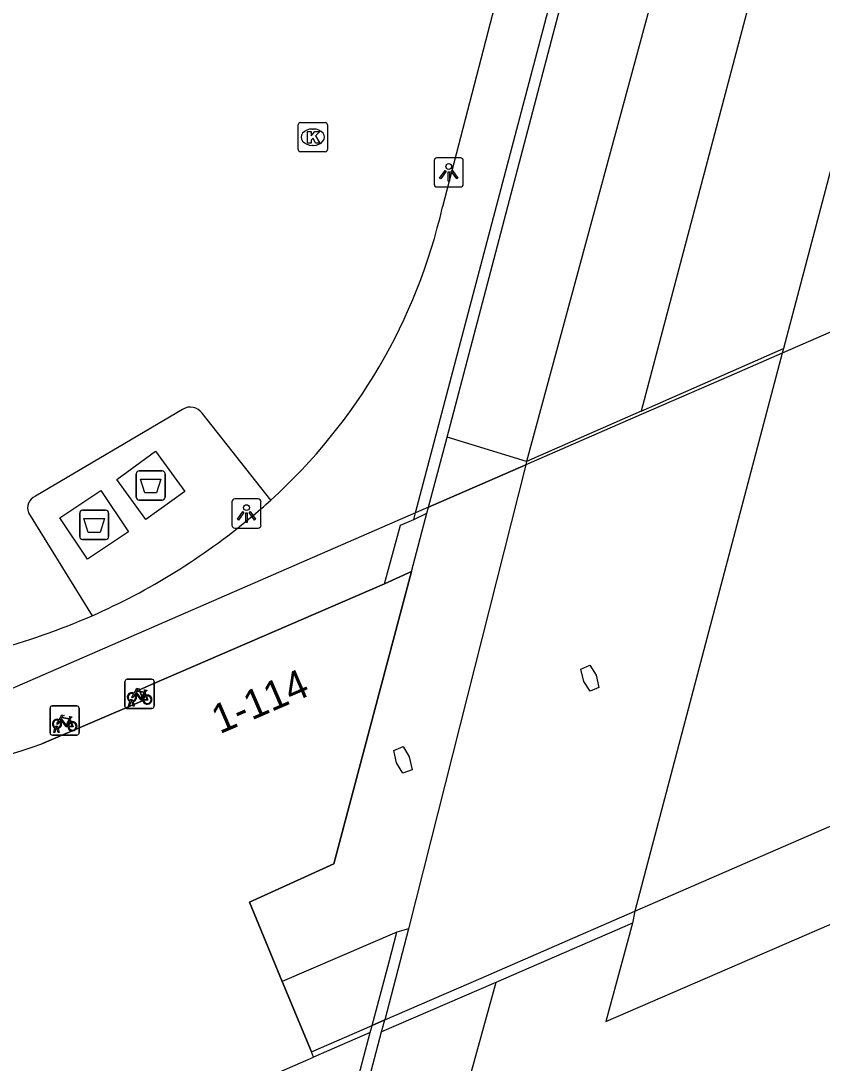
# Model space of a CAD drawing. Extents: x 162026 to 163499, y 387297 to 388169.
# Drawn here: x 162514.93 to 162542.4, y 387569.33 to 387605.06 of the extents above; entities that cross this region are included whole.
import ezdxf

# ---------------------------------------------------------------- set-up
doc = ezdxf.new("R2010")
doc.units = 0
for name, color, linetype in [('IMGEO_Afval_apart_plaats', 7, 'Continuous'), ('IMGEO_Fietsenrek', 7, 'Continuous'), ('IMGEO_Kolk', 7, 'Continuous'), ('IMGEO_Lichtpunt', 7, 'Continuous'), ('IMGEO_Meer_plas_ven_vijver', 7, 'Continuous'), ('IMGEO_Muur', 7, 'Continuous'), ('IMGEO_Pand', 7, 'Continuous'), ('IMGEO_Pand_nummerreeks', 7, 'Continuous'), ('IMGEO_Pand_overbouw', 7, 'Continuous'), ('IMGEO_Voetpad_gesloten', 7, 'Continuous'), ('IMGEO_Voetpad_halfverhard', 7, 'Continuous'), ('IMGEO_Voetpad_open', 7, 'Continuous')]:
    doc.layers.add(name, color=color, linetype=linetype)

msp = doc.modelspace()

# ---------------------------------------------------------------- linework, layer by layer
at = {"layer": 'IMGEO_Afval_apart_plaats'}
for p, q in [((162518.885, 387588.734), (162518.885, 387589.534)), ((162518.885, 387589.534), (162518.885, 387588.734)), ((162518.985, 387589.634), (162519.775, 387589.634)), ((162519.775, 387589.634), (162518.985, 387589.634)), ((162519.875, 387589.534), (162519.875, 387588.734)), ((162519.875, 387588.734), (162519.875, 387589.534)), ((162519.775, 387588.634), (162518.985, 387588.634)), ((162518.985, 387588.634), (162519.775, 387588.634)), ((162516.946, 387587.381), (162516.946, 387588.181)), ((162516.946, 387588.181), (162516.946, 387587.381)), ((162517.046, 387588.281), (162517.836, 387588.281)), ((162517.836, 387588.281), (162517.046, 387588.281)), ((162517.936, 387588.181), (162517.936, 387587.381)), ((162517.936, 387587.381), (162517.936, 387588.181)), ((162517.836, 387587.281), (162517.046, 387587.281)), ((162517.046, 387587.281), (162517.836, 387587.281))]:
    msp.add_line(p, q, dxfattribs=at)
for points in [[(162519.028, 387589.348), (162519.732, 387589.348), (162519.583, 387588.878), (162519.177, 387588.878), (162519.028, 387589.348)], [(162517.089, 387587.995), (162517.793, 387587.995), (162517.644, 387587.525), (162517.238, 387587.525), (162517.089, 387587.995)]]:
    msp.add_lwpolyline(points, dxfattribs=at)
for centre, start, end in [((162518.985, 387589.534), 90, 180), ((162518.985, 387589.534), 90, 180), ((162519.775, 387589.534), 0, 90), ((162519.775, 387589.534), 360, 90), ((162518.985, 387588.734), 180, 270), ((162518.985, 387588.734), 180, 270), ((162519.775, 387588.734), 270, 0), ((162519.775, 387588.734), 270, 0), ((162517.046, 387588.181), 90, 180), ((162517.046, 387588.181), 90, 180), ((162517.836, 387588.181), 0, 90), ((162517.836, 387588.181), 360, 90), ((162517.046, 387587.381), 180, 270), ((162517.046, 387587.381), 180, 270), ((162517.836, 387587.381), 270, 0), ((162517.836, 387587.381), 270, 0)]:
    msp.add_arc(centre, 0.1, start, end, dxfattribs=at)
at = {"layer": 'IMGEO_Fietsenrek'}
for p, q in [((162518.497, 387581.564), (162518.497, 387582.405)), ((162518.497, 387582.405), (162518.497, 387581.564)), ((162518.572, 387582.489), (162519.413, 387582.489)), ((162519.413, 387582.489), (162518.572, 387582.489)), ((162519.497, 387582.414), (162519.497, 387581.573)), ((162519.497, 387581.573), (162519.497, 387582.414)), ((162519.184, 387582.038), (162519.22, 387581.943)), ((162516.003, 387581.577), (162516.844, 387581.577)), ((162516.844, 387581.577), (162516.003, 387581.577)), ((162518.624, 387581.573), (162518.663, 387581.733)), ((162518.658, 387581.573), (162518.624, 387581.573)), ((162518.693, 387581.721), (162518.658, 387581.573)), ((162518.735, 387581.745), (162518.734, 387581.749)), ((162518.776, 387581.573), (162518.742, 387581.715)), ((162518.766, 387581.756), (162518.767, 387581.749)), ((162518.774, 387581.719), (162518.809, 387581.573)), ((162518.809, 387581.573), (162518.776, 387581.573)), ((162515.928, 387580.652), (162515.928, 387581.493)), ((162515.928, 387581.493), (162515.928, 387580.652)), ((162516.928, 387581.502), (162516.928, 387580.661)), ((162516.928, 387580.661), (162516.928, 387581.502)), ((162519.422, 387581.489), (162518.581, 387581.489)), ((162518.581, 387581.489), (162519.422, 387581.489)), ((162516.055, 387580.661), (162516.094, 387580.821)), ((162516.166, 387580.833), (162516.165, 387580.837)), ((162516.197, 387580.844), (162516.198, 387580.837)), ((162516.615, 387581.126), (162516.651, 387581.031)), ((162516.853, 387580.577), (162516.012, 387580.577)), ((162516.012, 387580.577), (162516.853, 387580.577)), ((162516.089, 387580.661), (162516.055, 387580.661)), ((162516.124, 387580.809), (162516.089, 387580.661)), ((162516.207, 387580.661), (162516.173, 387580.803)), ((162516.205, 387580.807), (162516.24, 387580.661)), ((162516.24, 387580.661), (162516.207, 387580.661))]:
    msp.add_line(p, q, dxfattribs=at)
for points in [[(162518.831, 387581.963), (162518.779, 387581.873), (162518.739, 387581.848), (162518.74, 387581.895), (162518.795, 387581.989)], [(162518.81, 387582.015), (162518.905, 387582.179), (162518.991, 387582.165), (162518.993, 387582.156), (162518.937, 387582.145), (162518.91, 387582.1), (162519.166, 387582.059)], [(162519.106, 387581.771), (162519.056, 387581.771), (162518.865, 387582.022), (162518.846, 387581.99)], [(162519.153, 387582.034), (162518.896, 387582.075), (162518.879, 387582.046), (162519.046, 387581.826), (162519.153, 387582.034)], [(162519.201, 387581.936), (162519.171, 387582.013), (162519.062, 387581.795), (162519.105, 387581.795)], [(162519.135, 387581.795), (162519.255, 387581.794), (162519.211, 387581.908)], [(162519.231, 387581.915), (162519.286, 387581.77), (162519.136, 387581.77)], [(162519.166, 387582.059), (162519.191, 387582.108), (162519.185, 387582.112), (162519.162, 387582.116), (162519.15, 387582.123), (162519.149, 387582.126), (162519.151, 387582.131), (162519.246, 387582.116), (162519.248, 387582.106), (162519.238, 387582.093), (162519.226, 387582.087), (162519.212, 387582.093), (162519.184, 387582.038)], [(162516.241, 387581.103), (162516.336, 387581.267), (162516.422, 387581.253), (162516.424, 387581.244), (162516.368, 387581.233), (162516.341, 387581.188), (162516.597, 387581.147)], [(162516.597, 387581.147), (162516.622, 387581.196), (162516.616, 387581.2), (162516.593, 387581.204), (162516.581, 387581.211), (162516.58, 387581.214), (162516.582, 387581.219), (162516.677, 387581.204), (162516.679, 387581.194), (162516.669, 387581.181), (162516.657, 387581.175), (162516.643, 387581.181), (162516.615, 387581.126)], [(162516.262, 387581.051), (162516.21, 387580.961), (162516.17, 387580.936), (162516.171, 387580.983), (162516.226, 387581.077)], [(162516.537, 387580.859), (162516.487, 387580.859), (162516.296, 387581.11), (162516.277, 387581.078)], [(162516.584, 387581.122), (162516.327, 387581.163), (162516.31, 387581.134), (162516.477, 387580.914), (162516.584, 387581.122)], [(162516.632, 387581.024), (162516.602, 387581.101), (162516.493, 387580.883), (162516.536, 387580.883)], [(162516.566, 387580.883), (162516.686, 387580.882), (162516.642, 387580.996)], [(162516.662, 387581.003), (162516.717, 387580.858), (162516.567, 387580.858)]]:
    msp.add_lwpolyline(points, dxfattribs=at)
for centre, radius, start, end in [((162518.575, 387582.411), 0.0779, 92.4484, 184.2845), ((162518.575, 387582.411), 0.0779, 92.4484, 184.2845), ((162519.419, 387582.411), 0.0779, 2.4484, 94.2845), ((162519.419, 387582.411), 0.0779, 2.4484, 94.2845), ((162518.737, 387581.874), 0.159, 62.6766, 242.1369), ((162518.737, 387581.874), 0.129, 63.3192, 238.903), ((162518.737, 387581.874), 0.129, 283.6043, 43.4302), ((162518.737, 387581.874), 0.159, 283.5766, 46.6042), ((162519.264, 387581.79), 0.159, 113.3408, 178.3217), ((162519.264, 387581.79), 0.159, 187.0065, 105.7708), ((162519.264, 387581.79), 0.129, 113.923, 177.9556), ((162519.264, 387581.79), 0.129, 188.6715, 104.5883), ((162516.006, 387581.499), 0.0779, 92.4484, 184.2845), ((162516.006, 387581.499), 0.0779, 92.4484, 184.2845), ((162516.85, 387581.499), 0.0779, 2.4484, 94.2845), ((162516.85, 387581.499), 0.0779, 2.4484, 94.2845), ((162518.575, 387581.567), 0.0779, 182.4484, 274.2845), ((162518.575, 387581.567), 0.0779, 182.4484, 274.2845), ((162518.717, 387581.745), 0.0499, 12.8025, 158.6934), ((162518.737, 387581.874), 0.159, 253.9967, 271.7867), ((162518.717, 387581.745), 0.0174, 12.8025, 163.4502), ((162518.737, 387581.874), 0.129, 253.415, 269.0204), ((162519.419, 387581.567), 0.0779, 272.4484, 4.2845), ((162519.419, 387581.567), 0.0779, 272.4484, 4.2845), ((162516.168, 387580.962), 0.159, 62.6766, 242.1369), ((162516.168, 387580.962), 0.129, 63.3192, 238.903), ((162516.148, 387580.833), 0.0499, 12.8025, 158.6934), ((162516.148, 387580.833), 0.0174, 12.8025, 163.4502), ((162516.168, 387580.962), 0.129, 253.415, 269.0204), ((162516.168, 387580.962), 0.129, 283.6043, 43.4302), ((162516.168, 387580.962), 0.159, 283.5766, 46.6042), ((162516.695, 387580.878), 0.159, 113.3408, 178.3217), ((162516.695, 387580.878), 0.159, 187.0065, 105.7708), ((162516.695, 387580.878), 0.129, 113.923, 177.9556), ((162516.695, 387580.878), 0.129, 188.6715, 104.5883), ((162516.006, 387580.655), 0.0779, 182.4484, 274.2845), ((162516.006, 387580.655), 0.0779, 182.4484, 274.2845), ((162516.168, 387580.962), 0.159, 253.9967, 271.7867), ((162516.85, 387580.655), 0.0779, 272.4484, 4.2845), ((162516.85, 387580.655), 0.0779, 272.4484, 4.2845)]:
    msp.add_arc(centre, radius, start, end, dxfattribs=at)
at = {"layer": 'IMGEO_Kolk'}
for p, q in [((162524.513, 387601.57), (162525.365, 387601.57)), ((162524.438, 387600.644), (162524.438, 387601.496)), ((162524.926, 387601.35), (162524.951, 387601.35)), ((162525.439, 387601.496), (162525.439, 387600.644)), ((162525.365, 387600.57), (162524.513, 387600.57)), ((162524.949, 387600.79), (162524.924, 387600.79))]:
    msp.add_line(p, q, dxfattribs=at)
for points in [[(162524.513, 387601.57), (162525.365, 387601.57)], [(162524.438, 387600.644), (162524.438, 387601.496)], [(162524.759, 387601.27), (162524.882, 387601.27), (162524.882, 387601.119), (162525.012, 387601.27), (162525.176, 387601.27), (162525.03, 387601.119), (162525.183, 387600.87), (162525.031, 387600.87), (162524.946, 387601.034), (162524.882, 387600.967), (162524.882, 387600.87), (162524.759, 387600.87), (162524.759, 387601.27)], [(162525.439, 387601.496), (162525.439, 387600.644)], [(162525.365, 387600.57), (162524.513, 387600.57)]]:
    msp.add_lwpolyline(points, dxfattribs=at)
for centre, start, end in [((162524.515, 387601.494), 91.552, 178.448), ((162524.515, 387601.494), 91.552, 178.448), ((162525.363, 387601.494), 1.552, 88.448), ((162525.363, 387601.494), 1.552, 88.448), ((162524.515, 387600.646), 181.552, 268.448), ((162524.515, 387600.646), 181.552, 268.448), ((162525.363, 387600.646), 271.552, 358.448), ((162525.363, 387600.646), 271.552, 358.448)]:
    msp.add_arc(centre, 0.0765, start, end, dxfattribs=at)
for centre, major_axis, ratio, start_param, end_param in [((162524.925, 387601.07), (-0.387, 0.002), 0.722429, 4.712389, 7.853982), ((162524.95, 387601.07), (-0.39, 0.002), 0.717154, 1.570796, 4.712389)]:
    msp.add_ellipse(centre, major_axis=major_axis, ratio=ratio, start_param=start_param, end_param=end_param, dxfattribs=at)
at = {"layer": 'IMGEO_Lichtpunt'}
for p, q in [((162529.1, 387600.266), (162529.1, 387599.459)), ((162529.1, 387600.266), (162529.1, 387599.459)), ((162530.002, 387600.361), (162529.194, 387600.361)), ((162530.002, 387600.361), (162529.194, 387600.361)), ((162530.096, 387599.459), (162530.096, 387600.266)), ((162530.096, 387599.459), (162530.096, 387600.266)), ((162529.194, 387599.365), (162530.002, 387599.365)), ((162529.194, 387599.365), (162530.002, 387599.365)), ((162522.166, 387588.574), (162522.166, 387587.767)), ((162522.166, 387588.574), (162522.166, 387587.767)), ((162523.068, 387588.669), (162522.26, 387588.669)), ((162523.068, 387588.669), (162522.26, 387588.669)), ((162523.162, 387587.767), (162523.162, 387588.574)), ((162523.162, 387587.767), (162523.162, 387588.574)), ((162522.26, 387587.673), (162523.068, 387587.673)), ((162522.26, 387587.673), (162523.068, 387587.673))]:
    msp.add_line(p, q, dxfattribs=at)
for points in [[(162529.474, 387599.93), (162529.513, 387599.902), (162529.325, 387599.64), (162529.287, 387599.667), (162529.474, 387599.93)], [(162529.576, 387599.882), (162529.623, 387599.882), (162529.623, 387599.56), (162529.576, 387599.56), (162529.576, 387599.882)], [(162529.686, 387599.902), (162529.724, 387599.929), (162529.911, 387599.667), (162529.872, 387599.639), (162529.686, 387599.902)], [(162522.54, 387588.238), (162522.579, 387588.21), (162522.391, 387587.948), (162522.353, 387587.975), (162522.54, 387588.238)], [(162522.642, 387588.19), (162522.689, 387588.19), (162522.689, 387587.868), (162522.642, 387587.868), (162522.642, 387588.19)], [(162522.752, 387588.21), (162522.79, 387588.237), (162522.977, 387587.975), (162522.938, 387587.947), (162522.752, 387588.21)]]:
    msp.add_lwpolyline(points, dxfattribs=at)
for centre in [(162529.599, 387600.064), (162522.665, 387588.372)]:
    msp.add_circle(centre, 0.0994, dxfattribs=at)
for centre, start, end in [((162529.194, 387600.266), 90, 180), ((162529.194, 387600.266), 90, 180), ((162530.002, 387600.266), 0, 90), ((162530.002, 387600.266), 0, 90), ((162529.194, 387599.459), 180, 270), ((162529.194, 387599.459), 180, 270), ((162530.002, 387599.459), 270, 0), ((162530.002, 387599.459), 270, 360), ((162522.26, 387588.574), 90, 180), ((162522.26, 387588.574), 90, 180), ((162523.068, 387588.574), 0, 90), ((162523.068, 387588.574), 0, 90), ((162522.26, 387587.767), 180, 270), ((162522.26, 387587.767), 180, 270), ((162523.068, 387587.767), 270, 0), ((162523.068, 387587.767), 270, 360)]:
    msp.add_arc(centre, 0.0946, start, end, dxfattribs=at)
at = {"layer": 'IMGEO_Meer_plas_ven_vijver'}
for points in [[(162560.534, 387602.953), (162543.885, 387604.461), (162541.075, 387593.824)], [(162535.896, 387574.133), (162534.981, 387570.755), (162562.211, 387582.543), (162587.069, 387580.384), (162588.875, 387597.053)]]:
    msp.add_lwpolyline(points, dxfattribs=at)
at = {"layer": 'IMGEO_Muur'}
for points in [[(162534.235, 387582.41), (162534.133, 387582.83), (162534.439, 387582.975), (162534.652, 387582.629), (162534.745, 387582.211), (162534.443, 387582.078), (162534.235, 387582.41)], [(162528.029, 387579.272), (162527.806, 387579.623), (162527.714, 387580.05), (162528.032, 387580.186), (162528.243, 387579.834), (162528.347, 387579.381), (162528.029, 387579.272)]]:
    msp.add_lwpolyline(points, dxfattribs=at)
at = {"layer": 'IMGEO_Pand'}
for points in [[(162523.891, 387572.131), (162522.764, 387574.851), (162525.655, 387576.16), (162528.323, 387586.18)], [(162528.323, 387586.18), (162527.391, 387585.763)], [(162527.391, 387585.763), (162519.405, 387582.313), (162518.991, 387582.123), (162519.117, 387581.76), (162515.65, 387580.277)], [(162524.967, 387569.533), (162524.89, 387569.718), (162523.891, 387572.131)], [(162521.057, 387567.837), (162524.967, 387569.533)]]:
    msp.add_lwpolyline(points, dxfattribs=at)
msp.add_arc((162506.829, 387605.086), 26.331, 264.9222, 289.5719, dxfattribs=at)
at = {"layer": 'IMGEO_Pand_overbouw'}
for points in [[(162589.229, 387614.65), (162562.047, 387602.816), (162541.034, 387593.668), (162539.2, 387592.869), (162536.202, 387591.564), (162532.238, 387589.839), (162528.908, 387588.389), (162528.461, 387588.194), (162514.525, 387582.127)], [(162515.65, 387580.277), (162519.117, 387581.76), (162518.991, 387582.123), (162519.405, 387582.313), (162527.391, 387585.763), (162528.323, 387586.18), (162525.655, 387576.16), (162522.764, 387574.851), (162523.891, 387572.131), (162524.89, 387569.718), (162526.971, 387570.622), (162527.405, 387570.811), (162530.712, 387572.249), (162534.116, 387573.729), (162535.981, 387574.539), (162588.93, 387597.558), (162592.789, 387599.235)]]:
    msp.add_lwpolyline(points, dxfattribs=at)
msp.add_arc((162506.829, 387605.086), 26.331, 264.9222, 289.5719, dxfattribs=at)
at = {"layer": 'IMGEO_Voetpad_gesloten'}
for points in [[(162541.075, 387593.824), (162541.034, 387593.668), (162535.981, 387574.539)], [(162536.202, 387591.682), (162541.075, 387593.824)], [(162536.202, 387591.682), (162532.267, 387589.952)], [(162519.211, 387587.962), (162518.214, 387589.339), (162519.549, 387590.306), (162520.546, 387588.929), (162519.211, 387587.962)], [(162532.238, 387589.839), (162528.225, 387573.93)], [(162532.267, 387589.952), (162532.238, 387589.839)], [(162517.212, 387586.607), (162516.269, 387588.021), (162517.671, 387588.956), (162518.614, 387587.542), (162517.212, 387586.607)], [(162527.405, 387570.811), (162530.712, 387572.249), (162534.116, 387573.729), (162535.981, 387574.539)], [(162535.981, 387574.539), (162535.896, 387574.133)], [(162535.896, 387574.133), (162531.213, 387572.1)], [(162528.225, 387573.93), (162527.405, 387570.811)], [(162531.213, 387572.1), (162527.297, 387570.4)], [(162527.297, 387570.4), (162527.405, 387570.811)]]:
    msp.add_lwpolyline(points, dxfattribs=at)
at = {"layer": 'IMGEO_Voetpad_halfverhard'}
for points in [[(162539.016, 387615.147), (162537.49, 387609.232), (162532.267, 387589.952)], [(162542.379, 387615.043), (162536.202, 387591.682)], [(162531.213, 387572.1), (162526.082, 387553.514)]]:
    msp.add_lwpolyline(points, dxfattribs=at)
at = {"layer": 'IMGEO_Voetpad_open'}
for points in [[(162528.461, 387588.194), (162535.674, 387615.505), (162535.953, 387615.553)], [(162529.541, 387590.792), (162536.005, 387615.344)], [(162532.332, 387610.054), (162529.386, 387598.68)], [(162520.475, 387591.741), (162515.428, 387588.764)], [(162523.499, 387588.631), (162521.143, 387591.608)], [(162528.908, 387588.389), (162529.541, 387590.792)], [(162532.267, 387589.952), (162529.541, 387590.792)], [(162528.908, 387588.389), (162532.238, 387589.839)], [(162528.853, 387588.181), (162528.908, 387588.389)], [(162528.461, 387588.194), (162514.525, 387582.127)], [(162515.192, 387588.196), (162517.369, 387584.666)], [(162527.391, 387585.763), (162527.941, 387587.771), (162528.399, 387587.961)], [(162528.323, 387586.18), (162528.853, 387588.181)], [(162528.399, 387587.961), (162528.461, 387588.194)], [(162528.399, 387587.961), (162528.853, 387588.181)], [(162527.817, 387573.82), (162523.891, 387572.131)], [(162526.971, 387570.622), (162527.558, 387572.807), (162527.817, 387573.82)], [(162528.225, 387573.93), (162527.817, 387573.82)], [(162526.907, 387570.386), (162526.971, 387570.622)], [(162527.405, 387570.811), (162526.971, 387570.622)], [(162522.358, 387553.136), (162522.733, 387553.053), (162527.297, 387570.4)], [(162522.358, 387553.136), (162526.907, 387570.386)], [(162526.907, 387570.386), (162524.967, 387569.533)]]:
    msp.add_lwpolyline(points, dxfattribs=at)
for centre, radius, start, end in [((162510.472, 387603.012), 19.404, 312.1729, 347.1011), ((162520.739, 387591.324), 0.494, 35.1425, 122.3366), ((162515.596, 387588.361), 0.436, 112.6095, 202.2654), ((162511.186, 387602.184), 18.311, 309.3971, 312.2547), ((162508.165, 387605.605), 22.872, 293.7279, 309.8063), ((162508.157, 387605.607), 22.877, 275.7115, 293.7447)]:
    msp.add_arc(centre, radius, start, end, dxfattribs=at)

# ---------------------------------------------------------------- texts
at = {"layer": 'IMGEO_Pand_nummerreeks'}
msp.add_text('1-114', height=1, rotation=23.3646, dxfattribs=at).set_placement((162521.747, 387580.601))

doc.saveas('drawing.dxf')
